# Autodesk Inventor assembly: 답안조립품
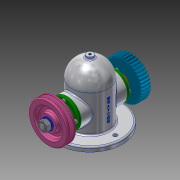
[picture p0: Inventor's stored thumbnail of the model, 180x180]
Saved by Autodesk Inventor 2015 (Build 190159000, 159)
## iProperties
Created: 2019-11
Part Number: 답안조립품
Document SubType Name: Assembly
Designer: Line503_02
Author: Line503_02
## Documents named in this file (14)
- C:\Users\Line503_02\Desktop\491104v1029\답안조립품.iam
- C:\Users\Line503_02\Desktop\491104v1029\본체.ipt
- C:\Users\Line503_02\Desktop\491104v1029\베어링 6203.ipt
- C:\Users\Line503_02\Desktop\491104v1029\커버.ipt
- C:\Users\Line503_02\Desktop\491104v1029\축.ipt
- C:\Users\Line503_02\Desktop\491104v1029\부시.ipt
- C:\Users\Line503_02\Desktop\491104v1029\오일 실 26 38 8.ipt
- C:\Users\Line503_02\Desktop\491104v1029\볼트 M4.ipt
- C:\Users\Line503_02\Desktop\491104v1029\키 5x5x12.ipt
- C:\Users\Line503_02\Desktop\491104v1029\V-벨트풀리.ipt
- V-벨트풀리.ipt
- C:\Users\Line503_02\Desktop\491104v1029\스퍼기어.ipt
- C:\Users\Line503_02\Desktop\491104v1029\와셔 12x24.ipt
- C:\Users\Line503_02\Desktop\491104v1029\너트 M12x1.25.ipt
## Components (1 placed, 1 different names)
1. V-벨트풀리:1 — 각도:3
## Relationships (1: Angle 1)
- 각도:3 [Angle]: V-벨트풀리:1
